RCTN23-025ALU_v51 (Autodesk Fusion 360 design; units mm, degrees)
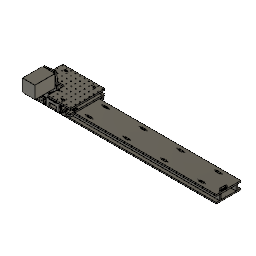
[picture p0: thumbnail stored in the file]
parameter "w_rail" = 110 comment "width of the rail - from 90 by 20mm increment"
parameter "l_gantry" = 190 comment "length of the travelling gantry - from 190 by 20mm increment"
parameter "l_travel" = 610 comment "total length of travel"
parameter "t_sheet_MAIN" = 6.35 (= "1 / 4 * 1") comment "thickness of *most* of the gantry material"
parameter "t_sheet_SECOND" = 6.35 (= "1 / 4 * 1") comment "thickness of the webs"
parameter "t_three" = 0.1
parameter "t_four" = 0.1
parameter "od_bearings" = 22
parameter "id_bearings" = 8
parameter "t_bearings" = 7
parameter "p_belt" = 2
parameter "w_belt" = 9
parameter "t_belt" = 1.4
parameter "t_meshedBelts" = 2.3
parameter "d_rail" = 25.4 (= "1")
parameter "d_beam" = 35.35 (= "od_bearings + t_sheet_MAIN + 2 mm + 5 mm") comment "min. is 2*t_bearings+3*shim+6mm+clearance"
parameter "hw_m6_drill" = 5 comment "5mm for zund bit"
parameter "r_cutoutTool" = 2.05 (= "4.1 mm / 2")
parameter "preload_flex_length" = 12
parameter "preload_flex_thickness" = 1.25
parameter "hw_m3_thru" = 3.25
parameter "hw_m3_head" = 5.5
parameter "hw_m3_washer" = 7
parameter "hw_m3_thread" = 2.5
parameter "tab_breather" = 0.2 comment "tab clearance"
parameter "hw_m5_thread" = 4.2
parameter "hw_m5_head" = 8.5
parameter "hw_m5_washer" = 10
parameter "hw_m5_thru" = 5.25
parameter "hw_m6_thru" = 6.5
parameter "hw_m6_head" = 10
parameter "hw_m6_washer" = 12
parameter "preload_displacement" = 0.25
parameter "dist_gap" = 3.5
parameter "l_beltblock" = 18
parameter "tab_breather_hdpe" = 0.1 (= "tab_breather / 2")
parameter "total_length" = 836 (= "l_gantry + l_travel + 2 * l_beltblock")
parameter "hw_plstf6_thread" = 2.94
parameter "hw_plstf6_thru" = 4
parameter "hw_plstf6_head" = 6.86
parameter "hw_plstf6_washer" = 7.92
parameter "t_beltroller_wall" = 1.7
parameter "hw_m3_flathead" = 6
parameter "d99" = 20
parameter "d124" = 9.525 (= "t_sheet_MAIN * 1.5")
parameter "d129" = 3
parameter "d213" = 0.2 (= "tab_breather")
parameter "d732" = 0.5
parameter "d893" = 2.25
parameter "d940" = 5.75 (= "d939 / 2 + 2 mm")
sketch "Plan"
  dimension "d670" = 110 (= "w_rail")
  dimension "d671" = 836 (= "l_travel + l_gantry + 2 * l_beltblock")
  dimension "d672" = 190 (= "l_gantry")
  dimension "d673" = 22 (= "od_bearings")
  dimension "d674" = 18 (= "l_beltblock")
  dimension "d675" = 22 (= "od_bearings")
  dimension "d676" = 20
  dimension "d677" = 7 (= "t_bearings")
  dimension "d678" = 22 (= "od_bearings")
  dimension "d679" = 6.35 (= "t_sheet_SECOND")
  dimension "d680" = 8
  dimension "d681" = 6.35 (= "t_sheet_MAIN")
  dimension "d682" = 1
  dimension "d683" = 1
  dimension "d684" = 5
  dimension "d765" = 6.35 (= "t_sheet_MAIN")
  dimension "d766" = 1 (= "d682")
extrude "Extrude81" new body sketch "Plan" no distance stored bodies "Top Rail Plate"
extrude "Extrude82" new body sketch "Plan" blind 6.35 (= "t_sheet_MAIN") from offset 3.5 (= "dist_gap")
extrude "Extrude83" new body sketch "Plan" blind 23 (= "od_bearings + 1 mm") bodies "Fixed Side Plate", "Floating Side Plate"
extrude "Extrude84" add sketch "Plan" no distance stored
sketch "Fixed Side" plane through (0, 117.35, 0) normal (0, 1, 0) x axis (-1, 0, 0)
  dimension "d694" = 22 (= "od_bearings")
  dimension "d696" = 6.35 (= "t_sheet_MAIN")
  dimension "d697" = 0.25 (= "preload_displacement")
  dimension "d699" = 6.35 (= "t_sheet_MAIN")
  dimension "d701" = 3.5 (= "dist_gap")
  dimension "d704" = 5 (= "hw_m6_drill")
  dimension "d706" = 5.5 (= "hw_m3_head")
  dimension "d707" = 3 (= "hw_m3_head / 2 + 0.25 mm")
  dimension "d711" = 26 (= "od_bearings + 4 mm")
  dimension "d713" = 5 (= "hw_m6_drill")
  dimension "d714" = 13
  dimension "d716" = 1.25 (= "preload_flex_thickness")
  dimension "d717" = 1.25 (= "preload_flex_thickness")
  dimension "d718" = 12 (= "preload_flex_length")
  dimension "d719" = 7
  dimension "d733" = 0.5
  dimension "d755" = 3.25 (= "hw_m3_thru")
  dimension "d756" = 0.2 (= "tab_breather")
  dimension "d759" = 20
  dimension "d776" = 11.5
  dimension "d1008" = 9
  dimension "d1009" = 3.5 (= "hw_m3_washer / 2")
  dimension "d1014" = 6
  dimension "d1141" = 15
  dimension "d1142" = 2
  dimension "d1167" = 5.85 (= "t_sheet_MAIN - 0.5 mm")
  dimension "d1168" = 9.525 (= "t_sheet_MAIN * 1.5")
  dimension "d1169" = 45
  dimension "d1170" = 4.1 (= "r_cutoutTool * 2")
extrude "Extrude85" cut sketch "Fixed Side" no distance stored
extrude "Extrude86" cut sketch "Fixed Side" no distance stored
extrude "Extrude87" sketch "Fixed Side" blind -16 (= "-t_bearings - 6 mm - 2 mm - 1 mm")
extrude "Extrude88" sketch "Fixed Side" blind 21 (= "od_bearings - 1 mm")
extrude "Extrude93" sketch "Fixed Side" blind 6.35 (= "t_sheet_MAIN")
extrude "Extrude144" add sketch "Fixed Side" no distance stored
extrude "Extrude145" cut sketch "Fixed Side" no distance stored
combine "Combine17"
offset_faces "OffsetFaces3"
combine "Combine16"
offset_faces "OffsetFaces4"
extrude "Extrude89" sketch "Fixed Side" no distance stored from offset -1
sketch "Fixed Top" plane through (0, 0, 9.85) normal (0, 0, 1) x axis (-1, 0, 0)
  dimension "d752" = 22 (= "od_bearings")
  dimension "d753" = 5 (= "hw_m6_drill")
  dimension "d767" = 7 (= "hw_m3_washer")
  dimension "d768" = 2.5 (= "hw_m3_thread")
  dimension "d1004" = 13
  dimension "d1010" = 3.75 (= "hw_m3_washer / 2 + 0.25 mm")
  dimension "d1011" = 8
extrude "Extrude91" cut sketch "Fixed Top" no distance stored
extrude "Extrude102" sketch "Fixed Top" no distance stored from offset -3
extrude "Extrude124" sketch "Fixed Top" blind -6 from offset 1
sketch "Floating Side" plane through (0, -7.35, 0) normal (0, -1, 0) x axis (1, 0, 0)
  dimension "d777" = 6.35 (= "t_sheet_MAIN")
  dimension "d778" = 3.5 (= "dist_gap")
  dimension "d779" = 6.35 (= "t_sheet_MAIN")
  dimension "d780" = 0.25 (= "preload_displacement")
  dimension "d781" = 22 (= "od_bearings")
  dimension "d783" = 12
  dimension "d784" = 5.5 (= "hw_m3_head")
  dimension "d785" = 3.25 (= "hw_m3_thru")
  dimension "d786" = 3.25 (= "hw_m3_head / 2 + 0.5 mm")
  dimension "d787" = 6
  dimension "d789" = 5 (= "hw_m6_drill")
  dimension "d790" = 1.25 (= "preload_flex_thickness")
  dimension "d791" = 1.25 (= "preload_flex_thickness")
  dimension "d792" = 6.5
  dimension "d793" = 12 (= "preload_flex_length")
  dimension "d794" = 0.5
  dimension "d796" = 9
  dimension "d797" = 45
  dimension "d835" = 7 (= "hw_m3_head + 1.5 mm")
  dimension "d1144" = 2
  dimension "d1145" = 12
  dimension "d1175" = 5.85 (= "t_sheet_MAIN - 0.5 mm")
  dimension "d1176" = 9.525 (= "t_sheet_MAIN * 1.5")
  dimension "d1177" = 4.1 (= "r_cutoutTool * 2")
  dimension "d1178" = 45
extrude "Extrude94" cut sketch "Floating Side" no distance stored
extrude "Extrude95" sketch "Floating Side" blind 21 (= "od_bearings - 1 mm")
extrude "Extrude96" sketch "Floating Side" blind -16
extrude "Extrude146" add sketch "Floating Side" no distance stored
extrude "Extrude147" cut sketch "Floating Side" no distance stored
combine "Combine18"
offset_faces "OffsetFaces5"
sketch "Floating Top" plane through (0, 0, 9.85) normal (0, 0, 1) x axis (-1, 0, 0)
  dimension "d808" = 22 (= "od_bearings")
  dimension "d809" = 5 (= "hw_m6_drill")
  dimension "d810" = 12 (= "preload_flex_length")
  dimension "d814" = 5.5
  dimension "d825" = 4
  dimension "d826" = 1.25 (= "preload_flex_thickness")
  dimension "d827" = 7
  dimension "d828" = 7 (= "3 mm + 2 mm + 2 mm")
  dimension "d829" = 4.2 (= "r_cutoutTool * 2 + 0.1 mm")
  dimension "d830" = 1.25 (= "preload_flex_thickness")
  dimension "d831" = 5
  dimension "d832" = 1
  dimension "d833" = 5.5 (= "hw_m3_head")
  dimension "d834" = 2.5 (= "hw_m3_thread")
  dimension "d851" = 0.25 (= "preload_displacement")
  dimension "d1164" = 1
extrude "Extrude98" cut sketch "Floating Top" no distance stored
fillet "Fillet66" radius 1
offset_faces "OffsetFaces6"
extrude "Extrude99" sketch "Floating Side" blind 6.35 (= "t_sheet_MAIN")
extrude "Extrude100" sketch "Floating Side" no distance stored from offset -1
extrude "Extrude101" sketch "Floating Top" no distance stored from offset -3
fillet "Fillet46" radius 2.05 (= "r_cutoutTool")
sketch "Sketch37" plane through (0, 117.35, 0) normal (0, 1, 0) x axis (-1, 0, 0)
  dimension "d854" = 4.1 (= "r_cutoutTool * 2")
  dimension "d955" = 45
extrude "Extrude103" cut sketch "Sketch37" no distance stored
sketch "Sketch38" plane through (0, 0, 9.85) normal (0, 0, 1) x axis (-1, 0, 0)
  dimension "d858" = 45
  dimension "d859" = 4.1 (= "r_cutoutTool * 2")
  dimension "d862" = 4.1 (= "r_cutoutTool * 2")
  dimension "d863" = 45
extrude "Extrude104" cut sketch "Sketch38" no distance stored
sketch "Sketch39" plane through (0, -7.35, 0) normal (0, -1, 0) x axis (1, 0, 0)
  dimension "d865" = 4.1 (= "r_cutoutTool * 2")
  dimension "d1001" = 45
extrude "Extrude105" cut sketch "Sketch39" no distance stored
fillet "Fillet47" radius 0.5
fillet "Fillet67" radius 2
fillet "Fillet48" radius 4
sketch "Sketch52" plane through (0, 0, 23) normal (0, 0, 1) x axis (-1, 0, 0)
  dimension "d1183" = 0.5
  dimension "d1184" = 0.5
  dimension "d1185" = 0.2 (= "tab_breather")
  dimension "d1186" = 0.2 (= "d1185")
  dimension "d1187" = 0.2 (= "d1185")
  dimension "d1188" = 0.2 (= "d1185")
  dimension "d1189" = 0.2 (= "tab_breather")
  dimension "d1190" = 0.2 (= "d1189")
  dimension "d1191" = 0.2 (= "d1189")
  dimension "d1192" = 0.2 (= "d1189")
  dimension "d1193" = 4.1 (= "r_cutoutTool * 2")
  dimension "d1194" = 45
  dimension "d1195" = 3.25 (= "hw_m3_thru")
  dimension "d1196" = 6
  dimension "d1197" = 7 (= "hw_m3_washer")
  dimension "d1198" = 45
  dimension "d1199" = 4.1 (= "r_cutoutTool * 2")
  dimension "d1200" = 6 (= "d1196")
  dimension "d1201" = 3.25 (= "hw_m3_thru")
extrude "Extrude148" new body sketch "Sketch52" along normal blind 6.35 (= "t_sheet_MAIN") bodies "Top Plate"
fillet "Fillet69" radius 1
fillet "Fillet70" radius 1
fillet "Fillet68" radius 4
mirror "Mirror22"
combine "Combine19"
combine "Combine20"
combine "Combine21"
mirror "Mirror26"
combine "Combine25"
sketch "Motor Base" plane through (0, 0, 9.85) normal (0, 0, 1) x axis (-1, 0, 0)
  dimension "d873" = 25.4 (= "od_bearings + ( t_beltroller_wall * 2 )")
  dimension "d874" = 2
  dimension "d875" = 7 (= "t_bearings")
  dimension "d876" = 7 (= "t_bearings")
  dimension "d877" = 0.75
  dimension "d878" = 6.3662 (= "( nt_pinion * 2 / PI ) * 1 mm / 2")
  dimension "d879" = 75
  dimension "d883" = 5
  dimension "d885" = 2.5 (= "hw_m3_thread")
  dimension "d930" = 3.5
  dimension "d958" = 3.5 (= "d930")
  dimension "d1093" = 11 (= "od_bearings / 2")
  dimension "d1094" = 0.7 (= "d874 / 2 - 0.3 mm")
  dimension "d1095" = 2
  dimension "d1096" = 45
  dimension "d1097" = 0.3
  dimension "d1098" = 5 (= "w_belt / 2 + 0.5 mm")
  dimension "d1099" = 0.5
  dimension "d1100" = 2.05 (= "t_meshedBelts - 0.25 mm")
  dimension "d1207" = 6 (= "hw_m3_flathead")
  dimension "d1208" = 13
  dimension "d1209" = 3.25 (= "hw_m3_thru")
  dimension "d1212" = 4.1 (= "r_cutoutTool * 2")
  dimension "d1213" = 45
  dimension "d1214" = 4.5
  dimension "d1215" = 4.5 (= "d1214")
  dimension "d1216" = 6.55 (= "t_sheet_MAIN + tab_breather")
  dimension "d1217" = 1
  dimension "d1218" = 9.45 (= "8 mm + 1.45 mm")
  dimension "d1260" = 5
  dimension "d1264" = 3
  dimension "d1265" = 5
extrude "Extrude119" cut sketch "Motor Base" no distance stored
extrude "Extrude149" cut sketch "Motor Base" to an object
sketch "Sketch53"
  dimension "d1219" = 6.35 (= "t_sheet_MAIN")
  dimension "d1220" = 0.1 (= "tab_breather / 2")
  dimension "d1221" = 0.1 (= "tab_breather / 2")
  dimension "d1222" = 0.1 (= "tab_breather / 2")
extrude "Extrude150" sketch "Sketch53" to an object from offset 0.5 bodies "Motor Plate"
extrude "Extrude151" sketch "Sketch53" to an object
combine "Combine26"
sketch "Motor" plane through (0, 26.45, 0) normal (0, 1, 0) x axis (-1, 0, 0)
  dimension "d900" = 4.1 (= "r_cutoutTool * 2")
  dimension "d901" = 25.4 (= "od_bearings + t_beltroller_wall * 2")
  dimension "d902" = 5 (= "hw_m6_drill")
  dimension "d903" = 12.7324 (= "( nt_pinion * 2 / PI ) * 1 mm")
  dimension "d905" = 0.75
  dimension "d906" = 45
  dimension "d907" = 56.4
  dimension "d908" = 47.14
  dimension "d1103" = 2 (= "t_meshedBelts - 0.3 mm")
  dimension "d1117" = 22 (= "od_bearings")
  dimension "d1118" = 2
  dimension "d1231" = 2.3 (= "t_meshedBelts")
  dimension "d1232" = 45
  dimension "d1233" = 45
  dimension "d1234" = 4.2 (= "hw_m5_thread")
  dimension "d1235" = 8
  dimension "d1236" = 2
  dimension "d1237" = 2.625 (= "hw_m5_thru / 2")
  dimension "d1238" = 19.075 (= "( 38.15 / 2 ) * 1 mm")
  dimension "d1239" = 2 (= "d1236")
  dimension "d1240" = 8 (= "d1235")
  dimension "d1241" = 8 (= "d1235")
  dimension "d1242" = 2 (= "d1236")
  dimension "d1243" = 10 (= "hw_m5_washer")
  dimension "d1244" = 5
  dimension "d1245" = 10 (= "hw_m5_washer")
  dimension "d1246" = 11
  dimension "d1247" = 70
  dimension "d1248" = 70 (= "d1247")
  dimension "d1249" = 1
extrude "Extrude152" add sketch "Motor" no distance stored
fillet "Fillet71" radius 3
fillet "Fillet72" radius 4
fillet "Fillet73" radius 12
extrude "Extrude153" cut sketch "Motor" no distance stored
extrude "Extrude154" sketch "Motor Base" to an object
fillet "Fillet74" radius 0.5
fillet "Fillet75" radius 2
fillet "Fillet76" radius 0.5
extrude "Extrude137" sketch "Motor" to an object bodies "Belt Tender"
extrude "Extrude138" sketch "Motor" to an object
extrude "Extrude139" sketch "Motor" to an object
chamfer "Chamfer1" distance 0.4
fillet "Fillet65" radius 0.3
extrude "Extrude114" new body sketch "Motor" blind 16 (= "t_bearings * 2 + 2 mm") from offset 1
extrude "Extrude112" sketch "Motor" blind -90 bodies "Motor"
sketch "Belt Block" plane through (0, 0, 0) normal (0, 0, 1) x axis (-1, 0, 0)
  dimension "d935" = 9.5 (= "w_belt + 0.5 mm")
  dimension "d937" = 5.5 (= "hw_m3_head")
  dimension "d939" = 7.5 (= "hw_m3_head + 2 mm")
  dimension "d942" = 3.25 (= "hw_m3_thru")
  dimension "d943" = 2.5 (= "hw_m3_thread")
  dimension "d1030" = 1.625 (= "hw_m3_thru / 2")
  dimension "d1031" = 0.5
  dimension "d1032" = 3.5
  dimension "d1033" = 3.75 (= "d939 / 2")
  dimension "d1034" = 4.75 (= "d1033 + 1 mm")
  dimension "d1035" = 13
  dimension "d1037" = 4
  dimension "d1040" = 4
  dimension "d1042" = 1.1
  dimension "d1061" = 14.7 (= "1 / 2 * 1  + 2 mm")
  dimension "d1068" = 3 (= "hw_m3_head / 2 + 0.25 mm")
  dimension "d1266" = 7.5 (= "d939")
  dimension "d1267" = 4 (= "d1037")
extrude "Extrude115" cut sketch "Belt Block" no distance stored
work_plane "WorkPlane6"
mirror "Mirror24"
extrude "Extrude116" new body sketch "Belt Block" along normal blind 2.5 (= "t_meshedBelts + 0.2 mm") bodies "Belt Tension Tside 1"
extrude "Extrude117" sketch "Belt Block" blind 6 (= "4 mm + 2 mm")
extrude "Extrude126" new body sketch "Belt Block" no distance stored
extrude "Extrude127" new body sketch "Belt Block" to an object Side2Offset 0 bodies "Belt Tension Tside 2"
combine "Combine24"
fillet "Fillet62" radius 1
sketch "Sketch48" plane through (-14.7, 0, 0) normal (-1, 0, 0) x axis (0, -1, 0)
  dimension "d1055" = 2.94 (= "hw_plstf6_thread")
  dimension "d1056" = 4 (= "hw_plstf6_thru")
  dimension "d1062" = 6.86 (= "hw_plstf6_head")
  dimension "d1072" = 2.75
  dimension "d1073" = 6
extrude "Extrude128" cut sketch "Sketch48" to an object offset 1
extrude "Extrude129" cut sketch "Sketch48" to an object
extrude "Extrude130" cut sketch "Sketch48" to an object
extrude "Extrude131" cut sketch "Sketch48" to an object
sketch "Sketch50" plane through (0, 0, 0) normal (0, 0, 1) x axis (-1, 0, 0)
  dimension "d1078" = 6 (= "hw_m3_head + 0.5 mm")
  dimension "d1079" = 3.25 (= "hw_m3_thru")
  dimension "d1081" = 9.5
  dimension "d1091" = 5
  dimension "d1092" = 4.25
extrude "Extrude134" new body sketch "Sketch50" to an object bodies "Belt Tension OSide1"
extrude "Extrude135" sketch "Sketch50" blind 2
extrude "Extrude140" sketch "Sketch50" to an object bodies "Belt Tension OSide2"
extrude "Extrude141" sketch "Sketch50" to an object from offset 1.2
fillet "Fillet64" radius 4
sketch "Sketch45" plane through (0, 0, 0) normal (0, 0, 1) x axis (-1, 0, 0)
  dimension "d964" = 6.35 (= "t_sheet_SECOND")
  dimension "d965" = 14 (= "t_bearings + 7 mm")
  dimension "d966" = 0.1 (= "tab_breather_hdpe")
  dimension "d967" = 0.1 (= "d966")
  dimension "d968" = 0.1 (= "d966")
  dimension "d969" = 0.1 (= "d966")
  dimension "d971" = 19.05 (= "t_sheet_MAIN * 3")
  dimension "d972" = 3.25 (= "hw_m3_thru")
  dimension "d973" = 6
  dimension "d974" = 6 (= "d973")
  dimension "d976" = 45
  dimension "d977" = 4.1 (= "r_cutoutTool * 2")
  dimension "d1269" = 45
  dimension "d1270" = 18
  dimension "d1271" = 167.2 (= "total_length / num_tabs")
work_plane "WorkPlane5"
extrude "Extrude121" sketch "Sketch45" blind -12 (= "-( od_bearings + 2 mm ) / 2") bodies "Web 1"
extrude "Extrude120" cut sketch "Sketch45" no distance stored
fillet "Fillet58" radius 0.5
rectangular_pattern "R-Pattern7" vSpaceDistance 0
extrude "Extrude122" sketch "Sketch45" blind 5.35 (= "t_sheet_MAIN - 1 mm")
sketch "Sketch46" plane through (0, 14.825, 0) normal (0, -1, 0) x axis (1, 0, 0)
  dimension "d989" = 4.1 (= "r_cutoutTool * 2")
  dimension "d1311" = 45
  dimension "d1312" = 90
extrude "Extrude155" cut sketch "Sketch46" no distance stored
fillet "Fillet57" radius 1
fillet "Fillet77" radius 0.5
rectangular_pattern "R-Pattern6" uSpaceDistance 167.2 (= "total_length / num_tabs") vSpaceDistance 0 bodies "Web 1 (1)", "Web 1 (2)", "Web 1 (3)", "Web 1 (4)"
mirror "Mirror27"
combine "Combine27" bodies "Web 1 (1)", "Web 1 (2)", "Web 1 (3)", "Web 1 (4)"
mirror "Mirror28" bodies "Web 1 (1)"
mirror "Mirror29" bodies "Top Rail Plate (1)", "Web 1 (2)", "Web 1 (1) (1)"
combine "Combine28" bodies "Web 1 (1) (1)"
combine "Combine29" bodies "Web 1 (2)"
sketch "Sketch54" plane through (0, 0, 29.35) normal (0, 0, 1) x axis (-1, 0, 0)
  dimension "d1288" = 4.2 (= "hw_m5_thread")
  dimension "d1289" = 7.5
  dimension "d1290" = 5
  dimension "d1291" = 10 (= "hw_m5_washer")
extrude "Extrude156" cut sketch "Sketch54" no distance stored
rectangular_pattern "R-Pattern8" countU 10 uSpaceDistance 20 vSpaceDistance 20
sketch "Sketch55" plane through (0, 0, -36.7) normal (0, 0, -1) x axis (1, 0, 0)
  dimension "d1298" = 4.2 (= "hw_m5_thread")
  dimension "d1299" = 5
  dimension "d1300" = 5
extrude "Extrude157" cut sketch "Sketch55" no distance stored
extrude "Extrude158" add sketch "Sketch55" no distance stored
rectangular_pattern "R-Pattern9" uSpaceDistance 20 vSpaceDistance -20
named bodies: "Top Rail Plate", "Plate", "Fixed Side Plate", "Floating Side Plate", "Motor", "Belt Tension Tside 1", "Web 1", "Body192 (1)", "Body192 (2)", "Body192 (3)", "Body192 (4)", "Body192 (5)", "Body192 (6)", "Body192 (7)", "Body192 (8)", "Body192 (9)", "Body192 (10)", "Body192 (11)", "Body192 (12)", "Body192 (13)", "Body192 (14)", "Body192 (15)", "Body192 (16)", "Belt Tension Tside 2", "Belt Tension OSide1", "Belt Tender", "Belt Tension OSide2", "Rail (2) (1)", "Rail (2) (2)", "Rail (2) (2) (1)", "Top Plate", "Motor Plate", "Top Rail Plate (1)", "Web 1 (1)", "Web 1 (2)", "Web 1 (3)", "Web 1 (4)", "Web 1 (1) (1)"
